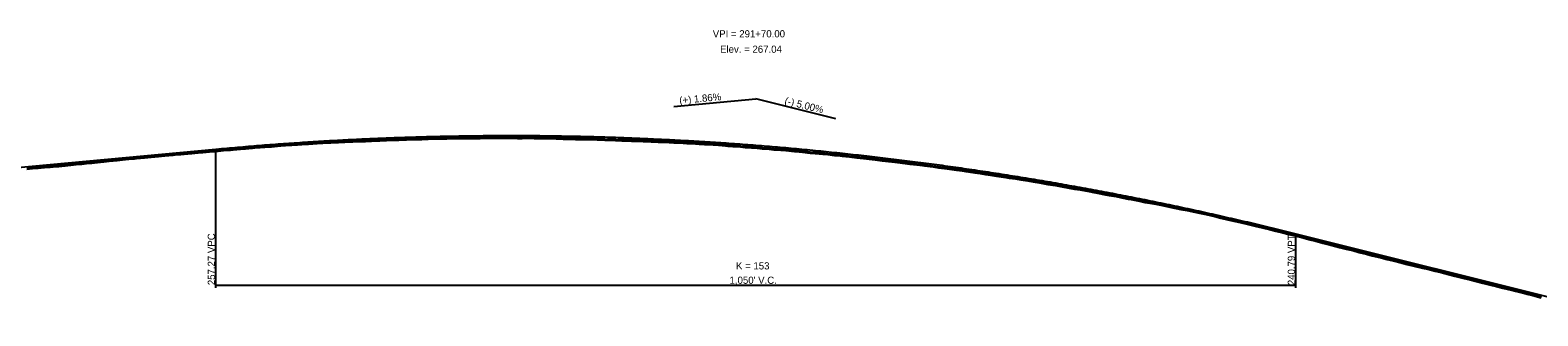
# Model space of a CAD drawing. Extents: x 1876258 to 1926563, y 729739 to 834437.
# Drawn here: x 1906827 to 1908293, y 831128 to 831407 of the extents above; entities that cross this region are included whole.
import ezdxf

# ---------------------------------------------------------------- set-up
doc = ezdxf.new("R2010")
doc.units = 0
for name, color, linetype in [('RD_EX_BldgApp', 7, 'Continuous'), ('RD_EX_H2O_BlueLn', 7, 'Continuous'), ('RD_EX_RailRoad', 7, 'Continuous'), ('RD_HC_Data', 7, 'Continuous'), ('RD_HC_Data_Tic', 7, 'Continuous'), ('RD_HC_TX_Sta50', 7, 'Continuous'), ('RD_PD_ALT5_CL', 7, 'Continuous')]:
    doc.layers.add(name, color=color, linetype=linetype)

msp = doc.modelspace()

# ---------------------------------------------------------------- linework, layer by layer
at = {"layer": 'RD_EX_BldgApp'}
for points in [[(1906872.2, 831275.6), (1906877.7, 831276.1), (1906884.6, 831276.9), (1906887.4, 831277.1), (1906892.8, 831277.7), (1906899, 831278.3), (1906904.4, 831278.9), (1906911.9, 831279.7), (1906917.2, 831280.2), (1906923.4, 831280.8), (1906928.9, 831281.2), (1906930.9, 831281.5), (1906938.5, 831282.3), (1906945.2, 831282.9), (1906952.1, 831283.5), (1906958.5, 831284.1), (1906966.6, 831284.9), (1906970.5, 831285.3), (1906974.1, 831285.6), (1906980.8, 831286.2), (1906984.5, 831286.5), (1906990.7, 831287.1), (1906995.4, 831287.5), (1907001.7, 831288), (1907006.9, 831288.5), (1907010.3, 831288.8), (1907015.4, 831289.2), (1907022.1, 831289.7), (1907024.7, 831290), (1907032.1, 831290.6), (1907036.9, 831291.1), (1907043.5, 831291.6), (1907048.5, 831292.1), (1907051, 831292.3), (1907055.6, 831292.6), (1907062.1, 831293), (1907065.1, 831293.3), (1907071.1, 831293.9), (1907075.7, 831294.2), (1907081.7, 831294.4), (1907087.5, 831294.9), (1907091.6, 831295.2), (1907098.1, 831295.5), (1907106.4, 831296), (1907111.9, 831296.4), (1907119.8, 831296.8), (1907127.2, 831297.1), (1907133.5, 831297.4), (1907141.3, 831297.8), (1907146.2, 831298), (1907153.4, 831298.2), (1907159.2, 831298.4), (1907167.5, 831298.8), (1907173.8, 831299), (1907181.6, 831299.3), (1907185.8, 831299.5), (1907193.5, 831299.7), (1907199.5, 831299.9), (1907208.3, 831300.2), (1907214.4, 831300.4), (1907224.2, 831300.6), (1907227.8, 831300.6), (1907232.7, 831300.8), (1907241.7, 831300.9), (1907246.7, 831301), (1907259.7, 831301.1), (1907265, 831301.1), (1907269.8, 831301.2), (1907281.2, 831301.2), (1907283.4, 831301.2), (1907289.3, 831301.2), (1907294.2, 831301.2), (1907301.4, 831301.1), (1907305.8, 831301.1), (1907310.4, 831301.2), (1907317.5, 831301.1), (1907321.9, 831301.1), (1907328.8, 831301), (1907332, 831300.9), (1907338.9, 831300.7), (1907345.8, 831300.5), (1907350.8, 831300.4), (1907355.1, 831300.3), (1907357.6, 831300.2), (1907362.5, 831300.1), (1907372.1, 831299.9), (1907378.8, 831299.7), (1907386, 831299.4), (1907390.9, 831299.3), (1907396.6, 831299.1), (1907402.8, 831298.8), (1907407.4, 831298.7), (1907412, 831298.5), (1907416.5, 831298.4), (1907423.3, 831298.1), (1907425.8, 831298), (1907431.3, 831297.8), (1907438.1, 831297.5), (1907444.1, 831297.3), (1907453.4, 831296.9), (1907458.8, 831296.7)], [(1907458.8, 831296.7), (1907466, 831296.3), (1907470.7, 831296), (1907478, 831295.5), (1907482.9, 831295.3), (1907491.6, 831294.7), (1907496.6, 831294.4), (1907503.4, 831293.9), (1907505.9, 831293.7), (1907510.5, 831293.3), (1907518, 831292.8), (1907522.7, 831292.4), (1907528.6, 831292), (1907534.1, 831291.6), (1907537, 831291.3), (1907539.2, 831291.1), (1907545.9, 831290.6), (1907550.6, 831290.1), (1907557.2, 831289.6), (1907562.2, 831289.2), (1907570.6, 831288.4), (1907575.2, 831288), (1907578.2, 831287.7), (1907585.7, 831286.9), (1907590.6, 831286.4), (1907598.2, 831285.7), (1907603, 831285.3), (1907609.6, 831284.6), (1907614.9, 831284.1), (1907616.9, 831283.8), (1907623.9, 831283.1), (1907631.1, 831282.3), (1907637.6, 831281.6), (1907643, 831280.9), (1907649.1, 831280.2), (1907655.8, 831279.4), (1907665.3, 831278.4), (1907670.8, 831277.7), (1907678, 831276.7), (1907682.8, 831276.1), (1907689.4, 831275.3), (1907694.9, 831274.6), (1907697.1, 831274.4), (1907705.3, 831273.3), (1907710.5, 831272.6), (1907716.4, 831271.8), (1907721.3, 831271.2), (1907728.1, 831270.2), (1907733.6, 831269.4), (1907737, 831268.9), (1907739.6, 831268.6), (1907746, 831267.6), (1907751.1, 831266.8), (1907756.1, 831266), (1907761.2, 831265.3), (1907766.8, 831264.5), (1907771.4, 831263.8), (1907775.9, 831263.1), (1907779.2, 831262.5), (1907785.3, 831261.6), (1907790.6, 831260.8), (1907797.4, 831259.8), (1907802.7, 831258.9), (1907808.9, 831257.8), (1907817, 831256.3), (1907824.3, 831255.1), (1907830.9, 831253.9), (1907837.5, 831252.7), (1907842.7, 831251.8), (1907848.2, 831250.9), (1907853.6, 831249.9), (1907857, 831249.3), (1907859.9, 831248.8), (1907865.1, 831247.8), (1907871.3, 831246.6), (1907876.6, 831245.6), (1907883.2, 831244.4), (1907888.9, 831243.3), (1907895, 831242.1), (1907898, 831241.6), (1907906, 831240), (1907911.3, 831238.8), (1907916.1, 831238), (1907921.7, 831237), (1907926.8, 831236), (1907931.4, 831235.1), (1907935.4, 831234.3), (1907946.2, 831232), (1907952.4, 831230.8), (1907958.3, 831229.5), (1907964.4, 831228.3), (1907970.7, 831226.9), (1907979.1, 831225), (1907985.2, 831223.5), (1907991.7, 831221.9), (1907997.6, 831220.6), (1908004, 831219.2), (1908010.5, 831217.6), (1908018.5, 831215.7), (1908025.6, 831214), (1908032.2, 831212.4)], [(1906824.2, 831271.3), (1906829.8, 831271.8), (1906835.1, 831272.2), (1906841.4, 831272.7), (1906846.8, 831273.2), (1906849.8, 831273.5), (1906855.2, 831273.9), (1906861.5, 831274.5), (1906867.1, 831275.1), (1906872.2, 831275.6)], [(1908032.2, 831212.4), (1908038.5, 831210.8), (1908045.2, 831209.2), (1908051.6, 831207.6), (1908058.3, 831206), (1908063.9, 831204.5), (1908072, 831202.4), (1908077.4, 831201), (1908084.2, 831199.2), (1908092, 831197.2), (1908097, 831196), (1908100.5, 831195), (1908106.9, 831193.4), (1908113.4, 831191.8), (1908119.6, 831190.1), (1908126.5, 831188.4), (1908132.2, 831186.9), (1908136.6, 831185.9), (1908140.9, 831184.8), (1908146.6, 831183.3), (1908154.2, 831181.5), (1908159.2, 831180.2), (1908166.2, 831178.4), (1908172.9, 831176.8), (1908181, 831174.8), (1908186.4, 831173.6), (1908193.5, 831171.8), (1908199.1, 831170.4), (1908206.4, 831168.6), (1908212.4, 831167.1), (1908220.3, 831165.1), (1908227.3, 831163.3), (1908239.9, 831160.1), (1908246.1, 831158.6), (1908253, 831156.8), (1908259.3, 831155.3), (1908264.7, 831154), (1908268.1, 831153.2), (1908271.5, 831152.3), (1908280.6, 831150), (1908283, 831149.4), (1908288.5, 831148), (1908296.4, 831146)]]:
    msp.add_lwpolyline(points, dxfattribs=at)
at = {"layer": 'RD_EX_H2O_BlueLn'}
for p, q in [((1907008.1, 831155.7), (1907008.1, 831290.7)), ((1908058.1, 831155.7), (1908058.1, 831208.2)), ((1907008.1, 831158.2), (1908058.1, 831158.2))]:
    msp.add_line(p, q, dxfattribs=at)
at = {"layer": 'RD_HC_Data_Tic'}
msp.add_lwpolyline([(1906824.1, 831272.6), (1906829.7, 831273), (1906835, 831273.4), (1906841.3, 831274), (1906846.7, 831274.4), (1906849.7, 831274.7), (1906855.1, 831275.2), (1906861.4, 831275.8), (1906867, 831276.3), (1906872.1, 831276.8), (1906877.6, 831277.4), (1906884.5, 831278.1), (1906887.3, 831278.3), (1906892.6, 831278.9), (1906898.9, 831279.6), (1906904.2, 831280.1), (1906911.8, 831281), (1906917, 831281.5), (1906923.3, 831282), (1906928.7, 831282.5), (1906930.8, 831282.7), (1906938.4, 831283.5), (1906945.1, 831284.2), (1906952, 831284.7), (1906958.3, 831285.4), (1906966.5, 831286.2), (1906970.4, 831286.5), (1906973.9, 831286.9), (1906980.7, 831287.5), (1906984.4, 831287.8), (1906990.6, 831288.3), (1906995.3, 831288.7), (1907001.6, 831289.3), (1907006.8, 831289.7), (1907010.2, 831290), (1907015.3, 831290.4), (1907022, 831291), (1907024.6, 831291.2), (1907032, 831291.9), (1907036.7, 831292.3), (1907043.4, 831292.9), (1907048.3, 831293.3), (1907050.9, 831293.6), (1907055.5, 831293.9), (1907062, 831294.3), (1907065, 831294.5), (1907070.9, 831295.1), (1907075.6, 831295.4), (1907081.6, 831295.7), (1907087.4, 831296.1), (1907091.6, 831296.4), (1907098, 831296.8), (1907106.3, 831297.3), (1907111.8, 831297.6), (1907119.7, 831298.1), (1907127.1, 831298.3), (1907133.4, 831298.6), (1907141.2, 831299), (1907146.2, 831299.2), (1907153.3, 831299.5), (1907159.1, 831299.7), (1907167.5, 831300), (1907173.8, 831300.3), (1907181.6, 831300.6), (1907185.8, 831300.7), (1907193.4, 831301), (1907199.4, 831301.2), (1907208.3, 831301.5), (1907214.4, 831301.6), (1907224.2, 831301.8), (1907227.8, 831301.9), (1907232.7, 831302), (1907241.7, 831302.1), (1907246.7, 831302.2), (1907259.7, 831302.4), (1907265, 831302.4), (1907269.8, 831302.5), (1907281.1, 831302.4), (1907283.4, 831302.5), (1907289.3, 831302.4), (1907294.2, 831302.4), (1907301.4, 831302.4), (1907305.8, 831302.4), (1907310.4, 831302.4), (1907317.5, 831302.3), (1907321.9, 831302.3), (1907328.9, 831302.2), (1907332, 831302.2), (1907338.9, 831302), (1907345.9, 831301.8), (1907350.8, 831301.6), (1907355.1, 831301.6), (1907357.7, 831301.5), (1907362.6, 831301.4), (1907364.7, 831301.3), (1907372.1, 831301.1), (1907374.2, 831301.1), (1907378.8, 831301), (1907383.7, 831300.7), (1907386, 831300.6), (1907390.9, 831300.5), (1907393.2, 831300.5), (1907396.7, 831300.4), (1907402.8, 831300.1), (1907402.9, 831300.1), (1907407.4, 831300), (1907412.1, 831299.8), (1907412.3, 831299.8), (1907416.6, 831299.6), (1907421.9, 831299.4), (1907423.3, 831299.3), (1907425.8, 831299.2), (1907431.4, 831299.1), (1907431.4, 831299.1), (1907438.2, 831298.8), (1907440.9, 831298.7), (1907444.2, 831298.6), (1907450.5, 831298.3), (1907453.4, 831298.2), (1907458.8, 831298), (1907460, 831297.9), (1907466, 831297.6), (1907469.5, 831297.4), (1907470.8, 831297.3), (1907478.1, 831296.8), (1907479.1, 831296.7), (1907482.9, 831296.5), (1907488.6, 831296.2), (1907491.7, 831296), (1907496.7, 831295.6), (1907498.1, 831295.5), (1907503.5, 831295.1), (1907506, 831294.9), (1907507.7, 831294.8), (1907510.6, 831294.6), (1907517.2, 831294.1), (1907518.1, 831294), (1907522.8, 831293.7), (1907526.7, 831293.4), (1907528.7, 831293.3), (1907534.2, 831292.8), (1907536.3, 831292.6), (1907537.1, 831292.5), (1907539.3, 831292.4), (1907545.8, 831291.8), (1907546, 831291.8), (1907550.7, 831291.4), (1907555.3, 831291), (1907557.3, 831290.9), (1907562.3, 831290.5), (1907564.9, 831290.2), (1907570.7, 831289.7), (1907574.4, 831289.3), (1907575.3, 831289.2), (1907578.4, 831289), (1907584, 831288.4), (1907585.8, 831288.2), (1907590.7, 831287.7), (1907593.5, 831287.4), (1907598.3, 831287), (1907603, 831286.5), (1907603.1, 831286.5), (1907609.7, 831285.8), (1907612.5, 831285.6), (1907615, 831285.3), (1907617.1, 831285.1), (1907622.1, 831284.5), (1907624, 831284.3), (1907631.2, 831283.6), (1907631.6, 831283.5), (1907637.7, 831282.9), (1907641.2, 831282.4), (1907643.2, 831282.2), (1907649.2, 831281.4), (1907650.7, 831281.2), (1907656, 831280.6), (1907660.2, 831280.2), (1907665.4, 831279.6), (1907669.8, 831279.1), (1907671, 831278.9), (1907678.1, 831277.9), (1907679.3, 831277.8), (1907683, 831277.3), (1907688.8, 831276.6), (1907689.6, 831276.5), (1907695.1, 831275.9), (1907697.2, 831275.6), (1907698.4, 831275.5), (1907705.5, 831274.5), (1907707.9, 831274.2), (1907710.6, 831273.8), (1907716.6, 831273.1), (1907717.4, 831273), (1907721.5, 831272.4), (1907727, 831271.6), (1907728.3, 831271.4), (1907733.8, 831270.6), (1907736.5, 831270.2), (1907737.2, 831270.2), (1907739.7, 831269.8), (1907746, 831268.8), (1907746.2, 831268.8), (1907751.3, 831268), (1907755.6, 831267.3), (1907756.3, 831267.2), (1907761.3, 831266.5), (1907765.1, 831266), (1907767, 831265.7), (1907771.6, 831265.1), (1907774.6, 831264.5), (1907776.1, 831264.3), (1907779.4, 831263.7), (1907784.2, 831263), (1907785.5, 831262.8), (1907790.8, 831262.1), (1907793.7, 831261.6), (1907797.6, 831261), (1907803, 831260.1), (1907803.3, 831260), (1907809.1, 831259), (1907812.8, 831258.4), (1907817.2, 831257.6), (1907822.3, 831256.7), (1907824.5, 831256.3), (1907831.1, 831255.2), (1907831.8, 831255), (1907837.8, 831254), (1907841.4, 831253.3), (1907842.9, 831253.1), (1907848.4, 831252.1), (1907850.9, 831251.7), (1907853.8, 831251.2), (1907857.2, 831250.6), (1907860.1, 831250), (1907860.5, 831249.9), (1907865.3, 831249), (1907870, 831248.1), (1907871.5, 831247.9), (1907876.8, 831246.8), (1907879.5, 831246.3), (1907883.4, 831245.6), (1907889, 831244.6), (1907889.1, 831244.5), (1907895.3, 831243.3), (1907898.2, 831242.8), (1907898.6, 831242.8), (1907906.3, 831241.2), (1907908.1, 831240.8), (1907911.6, 831240.1), (1907916.3, 831239.2), (1907917.6, 831239), (1907921.9, 831238.2), (1907927, 831237.2), (1907927.2, 831237.2), (1907931.6, 831236.3), (1907935.7, 831235.5), (1907936.7, 831235.3), (1907946.3, 831233.3), (1907946.4, 831233.2), (1907952.6, 831232), (1907955.8, 831231.3), (1907958.5, 831230.8), (1907964.7, 831229.5), (1907965.3, 831229.4), (1907971, 831228.1), (1907974.9, 831227.2), (1907979.4, 831226.2), (1907984.4, 831225), (1907985.5, 831224.7), (1907992, 831223.1), (1907993.9, 831222.7), (1907997.8, 831221.8), (1908003.5, 831220.6), (1908004.3, 831220.4), (1908010.8, 831218.8), (1908013, 831218.3), (1908018.8, 831216.9), (1908022.5, 831216), (1908025.9, 831215.2), (1908032.1, 831213.7), (1908032.5, 831213.6), (1908038.8, 831212), (1908041.6, 831211.4), (1908045.5, 831210.4), (1908051.1, 831209), (1908051.9, 831208.8), (1908058.6, 831207.2), (1908060.7, 831206.6), (1908064.3, 831205.7), (1908070.2, 831204.1), (1908072.3, 831203.6), (1908077.7, 831202.2), (1908079.7, 831201.7), (1908084.5, 831200.4), (1908089.3, 831199.2), (1908092.3, 831198.4), (1908097.3, 831197.2), (1908098.8, 831196.8), (1908100.8, 831196.3), (1908107.2, 831194.6), (1908108.3, 831194.3), (1908113.7, 831193), (1908117.9, 831191.9), (1908120, 831191.3), (1908126.8, 831189.6), (1908127.4, 831189.4), (1908132.5, 831188.1), (1908136.9, 831187.1), (1908141.2, 831186), (1908146.9, 831184.5), (1908154.5, 831182.7), (1908159.5, 831181.4), (1908166.5, 831179.7), (1908173.2, 831178), (1908181.3, 831176.1), (1908186.7, 831174.8), (1908193.8, 831173), (1908199.4, 831171.6), (1908206.7, 831169.8), (1908212.7, 831168.3), (1908220.6, 831166.3), (1908227.6, 831164.5), (1908240.2, 831161.3), (1908246.5, 831159.8), (1908253.3, 831158.1), (1908259.6, 831156.5), (1908265, 831155.2), (1908268.3, 831154.4), (1908271.8, 831153.5), (1908280.9, 831151.3), (1908283.3, 831150.7), (1908288.8, 831149.2), (1908296.7, 831147.2)], dxfattribs=at)
at = {"layer": 'RD_HC_TX_Sta50'}
for p in [(1907453.4, 831332.1), (1907610.7, 831320.1)]:
    msp.add_line(p, (1907533.1, 831339.5), dxfattribs=at)
at = {"layer": 'RD_PD_ALT5_CL'}
for p, q in [((1906248.1, 831220), (1907008.1, 831290.7)), ((1908058.1, 831208.2), (1908378.1, 831128.2))]:
    msp.add_line(p, q, dxfattribs=at)
msp.add_spline([(1907008.1, 831290.7), (1907029.1, 831292.5), (1907050.1, 831294.3), (1907071.1, 831295.9), (1907092.1, 831297.3), (1907113.1, 831298.6), (1907134.1, 831299.8), (1907155.1, 831300.8), (1907176.1, 831301.7), (1907197.1, 831302.4), (1907218.1, 831303), (1907239.1, 831303.4), (1907260.1, 831303.7), (1907281.1, 831303.9), (1907302.1, 831303.9), (1907323.1, 831303.8), (1907344.1, 831303.5), (1907365.1, 831303.1), (1907386.1, 831302.5), (1907407.1, 831301.8), (1907428.1, 831300.9), (1907449.1, 831299.9), (1907470.1, 831298.8), (1907491.1, 831297.5), (1907512.1, 831296.1), (1907533.1, 831294.5), (1907554.1, 831292.8), (1907575.1, 831290.9), (1907596.1, 831288.9), (1907617.1, 831286.7), (1907638.1, 831284.4), (1907659.1, 831282), (1907680.1, 831279.4), (1907701.1, 831276.7), (1907722.1, 831273.8), (1907743.1, 831270.8), (1907764.1, 831267.6), (1907785.1, 831264.3), (1907806.1, 831260.9), (1907827.1, 831257.3), (1907848.1, 831253.5), (1907869.1, 831249.7), (1907890.1, 831245.6), (1907911.1, 831241.5), (1907932.1, 831237.2), (1907953.1, 831232.7), (1907974.1, 831228.1), (1907995.1, 831223.3), (1908016.1, 831218.5), (1908037.1, 831213.4), (1908058.1, 831208.2)], degree=3, dxfattribs=at)

# ---------------------------------------------------------------- texts
at = {"layer": 'RD_EX_H2O_BlueLn'}
for s, p in [('K = 153', (1907513.7, 831173.5)), ("1,050' V.C.", (1907507.4, 831159.5))]:
    msp.add_text(s, height=7, dxfattribs=at).set_placement(p)
at = {"layer": 'RD_EX_RailRoad'}
for s, p in [('257.27 VPC', (1907007.1, 831158.2)), ('240.79 VPT', (1908057.1, 831158.2))]:
    msp.add_text(s, height=7, rotation=90, dxfattribs=at).set_placement(p)
at = {"layer": 'RD_HC_Data'}
for s, p in [('VPI = 291+70.00', (1907491.1, 831399.5)), ('Elev. = 267.04', (1907498.2, 831384.5))]:
    msp.add_text(s, height=7, dxfattribs=at).set_placement(p)
at = {"layer": 'RD_HC_TX_Sta50'}
for s, rotation, p in [('(+) 1.86%', 5.3139, (1907458.9, 831334.6)), ('(-) 5.00%', 345.9638, (1907560.4, 831334.7))]:
    msp.add_text(s, height=7, rotation=rotation, dxfattribs=at).set_placement(p)

doc.saveas('drawing.dxf')
